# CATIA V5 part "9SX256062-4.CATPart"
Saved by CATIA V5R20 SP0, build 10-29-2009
Part number: 9SX256062-4
Revision: ANY
Definition: UNKNOWN
Nomenclature: 9SX256062-4
Source: Unknown
Bounding box of the stored display mesh (mm): x -23 to 23, y -23 to 23, z 0 to 29
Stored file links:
  C:\Users\Utente\Desktop\IO LAVORO\3D X SITO CF\CUMSA\3D files SX.256062\SX 256062\9SX256062-4.CATPart
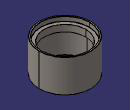
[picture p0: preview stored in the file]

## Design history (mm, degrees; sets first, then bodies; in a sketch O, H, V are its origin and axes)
Body1 "Chaflán4" (main body)
  Solid1: solid without history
